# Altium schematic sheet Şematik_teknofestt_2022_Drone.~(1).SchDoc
size A4; SheetNumber: 1; SheetTotal: 1
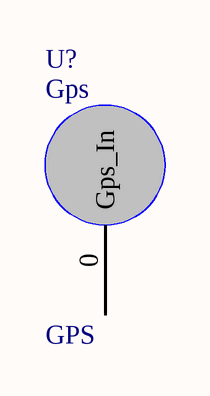
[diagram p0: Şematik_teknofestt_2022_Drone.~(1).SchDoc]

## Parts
U?  GPS

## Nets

Not connected (* = marked no-connect by the designer): U? 0(Gps_In)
